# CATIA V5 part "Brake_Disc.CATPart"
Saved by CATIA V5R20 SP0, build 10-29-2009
Part number: Brake_Disc
Material "Steel": density 7860 kg/m3, Young's modulus 2e+11 Pa, Poisson ratio 0.266, thermal expansion 1.17e-05 1/K
Bounding box of the stored display mesh (mm): x -6.5 to 6.5, y -62.5 to 62.5, z -62.5 to 62.5
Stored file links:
  C:\Users\syed\Desktop\GITHUB\Advance-Smart-GPS-Electromagnetic-Brake-System\NIHAAL\Hardware\CATIA\Model_01\Part\Brake_Disc.CATPart
  D:\DREAD STUDIO SOFTWARE\Catia_V5\Catia_V5_Installed\intel_a\startup\materials\Catalog.CATMaterial
  D:\DREAD STUDIO SOFTWARE\Catia_V5\Catia_V5_Installed\intel_a\resources\graphic\figures\CATIA_EnvironmentMap_Square1_512x512.jpg
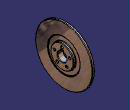
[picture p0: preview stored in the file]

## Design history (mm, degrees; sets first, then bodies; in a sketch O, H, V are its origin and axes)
Body1 (main body), material "Steel"
  Sketch1 on yz-plane, origin (0, 0, 0), H (0, 1, 0), V (0, 0, 1)
    circle A1 centre (0, 0) radius 62.5
    radius A1 = 62.5
  Pad1: profile Sketch1, direction (1, 0, 0), length 2.5, mirrored extent
  Sketch2 on end face of Pad1, origin (2.5, 0, 0), H (0, 1, 0), V (0, 0, 1)
    circle A1 centre (0, 0) radius 35
    radius A1 = 35
  Pocket1: profile Sketch2, direction (-1, 0, 0), length 1
  Sketch3 on start face of Pad1, origin (-2.5, 0, 0), H (0, -1, 0), V (0, 0, 1)
    circle A1 centre (0, 0) radius 35
    radius A1 = 35
  Pocket2: profile Sketch3, direction (1, 0, 0), length 1
  Sketch4 on end face of Pocket1, origin (1.5, 0, 0), H (0, 1, 0), V (0, 0, 1)
    circle A1 centre (0, 0) radius 25
    radius A1 = 25
  Pad2: profile Sketch4, direction (1, 0, 0), length 5
  Sketch5 on end face of Pocket2, origin (-1.5, 0, 0), H (0, -1, 0), V (0, 0, 1)
    circle A1 centre (0, 0) radius 25
    radius A1 = 25
  Pad3: profile Sketch5, direction (-1, 0, 0), length 5
  Sketch6 on end face of Pad2, origin (6.5, 0, 0), H (0, 1, 0), V (0, 0, 1)
    circle A1 centre (0, 0) radius 10
    radius A1 = 10
  Pocket3: profile Sketch6, direction (-1, 0, 0), through (limit type 3)
  Sketch7 on end face of Pad3, origin (-6.5, 0, 0), H (0, -1, 0), V (0, 0, 1)
    reference projected circle E1 centre (0, 0) radius 10 from edge [end face of Pad3 | face of Pocket3 from Sketch6.A1]
    reference projected circle E2 centre (0, 0) radius 25 from edge [face of Pad3 from Sketch5.A1 | end face of Pad3]
    axis line L1 (0, 10) -> (0, 25)
    point P1 (0, 10)
    point P2 (0, 25)
    circle A1 centre (0, 17.5) radius 2
    point P3 (0, 17.5)
    radius A1 = 2
    coincidence: P1 E1, P1 V, P2 E2
    vertical: L1 V
    midpoint: P3 L1
  Pocket4: profile Sketch7, direction (1, 0, 0), through (limit type 3)
  CircPattern1: of Pocket4, instances 5, angular step 72 {= 360.0*1 deg/CircPattern1.AngularNumber}, axis from X axis
  Fillet1: radius 1, on edge [face of Pad2 from Sketch4.A1 | end face of Pad2]; edge [end face of Pad1 | face of Pocket1 from Sketch2.A1]; edge [end face of Pocket1 | face of Pad2 from Sketch4.A1]; edge [face of Pocket1 from Sketch2.A1 | end face of Pocket1]; edge [end face of Pad3 | face of Pocket3 from Sketch6.A1]; edge [end face of Pad2 | face of Pocket3 from Sketch6.A1]; edge [face of Pad3 from Sketch5.A1 | end face of Pad3]; face of Pad3 from Sketch5.A1; edge [face of Pocket2 from Sketch3.A1 | end face of Pocket2]; edge [start face of Pad1 | face of Pocket2 from Sketch3.A1]; edge [end face of Pad3 | face of CircPattern1] (x4); edge [end face of Pad3 | face of Pocket4 from Sketch7.A1]; edge [end face of Pad2 | face of Pocket4 from Sketch7.A1]; edge [end face of Pad2 | face of CircPattern1] (x4); end face of Pad1; edge [start face of Pad1 | face of Pad1 from Sketch1.A1]
  Sketch8 on end face of Pad2, origin (6.5, 0, 0), H (0, 1, 0), V (0, 0, 1)
    line L1 (-3, 13) -> (3, 13)
    line L2 (3, 13) -> (3, 8)
    line L3 (3, 8) -> (-3, 8)
    line L4 (-3, 8) -> (-3, 13)
    axis line L5 (0, 17.5842) -> (0, 8)
    point P5 (0, 17.5842)
    point P6 (0, 8)
    distance H L3 = 8
    length L3 = 6
    length L4 = 5
    horizontal: L1 H, L3 H
    vertical: L2 V, L4 V, L5 V
    coincidence: P5 V
    midpoint: P6 L3
  Pocket5: profile Sketch8, direction (-1, 0, 0), through (limit type 3)
  Fillet2: radius 1, on edge [face of Pocket5 from Sketch8.L4 | face of Pocket3 from Sketch6.A1]; edge [face of Pocket5 from Sketch8.L4 | face of Pocket5 from Sketch8.L1]; edge [end face of Pad2 | face of Pocket5 from Sketch8.L1]; edge [face of Pocket5 from Sketch8.L1 | face of Pocket5 from Sketch8.L2]; edge [face of Pocket3 from Sketch6.A1 | face of Pocket5 from Sketch8.L2]; edge [end face of Pad3 | face of Pocket5 from Sketch8.L1]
